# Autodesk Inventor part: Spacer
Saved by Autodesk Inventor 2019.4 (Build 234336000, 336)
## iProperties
Created: 2020-02
Part Number: Spacer
Material: Generic
Document SubType Name: Modeling
Designer: Administrator
Density: 1 g/cm^3
Appearance: Default
Title: Spacer v9
Author: Administrator
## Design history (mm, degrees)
feature "Body1"
feature "Body2"
feature "Body3"
feature "Body4"
body "Solid1"
body "Solid2"
body "Solid3"
body "Solid4"
